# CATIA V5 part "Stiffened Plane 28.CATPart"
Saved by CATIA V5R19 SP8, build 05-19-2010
Part number: Stiffened Plane 28
Bounding box of the stored display mesh (mm): x -20 to 20, y 795 to 1210.536, z 380 to 458.19
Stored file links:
  G:\EU_thinkMotion\CFAO_2010\MMS_groupe3\MMS_groupe3\A reprendre\fovide\fovide\Stiffened Plane 28.CATPart
  G:\EU_thinkMotion\CFAO_2010\MMS_groupe3\MMS_groupe3\A reprendre\fovide\fovide\fovide.CATProduct
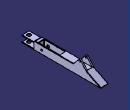
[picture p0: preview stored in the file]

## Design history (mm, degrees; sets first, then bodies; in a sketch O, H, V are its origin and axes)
Set1
  Plane1: linked copy from another document
  Line1 to Line3: linked copy from another document
  Point1 "Point.E": linked copy from another document
  Line4: linked copy from another document
Body1 (main body)
  Sketch1 on Plane1, origin (0, 0, 0), H (0, 1, 0), V (0, 0, 1)
    line L1 (865, 422) -> (1132.4619, 422)
    line L2 (1132.4619, 422) -> (1217.1203, 380)
    line L3 (1217.1203, 380) -> (865, 380)
    reference projected line E1 (1100, 400) -> (815, 400) from Line1
    line L4 (865, 422) -> (857, 416)
    line L5 (857, 416) -> (795, 416)
    line L6 (795, 416) -> (795, 411)
    line L7 (795, 411) -> (857.1371, 411)
    line L8 (857.1371, 411) -> (857.1371, 385)
    line L9 (857.1371, 385) -> (795, 385)
    point P10 (795, 385)
    line L10 (795, 385) -> (795, 380)
    point P11 (795, 380)
    line L11 (795, 380) -> (865, 380)
    reference projected line E2 (815, 250) -> (815, 550) from Line2
    distance L1 E1 = 22
    length L5 = 62
    distance L6 E2 = 20
    length L8 = 26
    length L6 = 5
    length L10 = 5
    distance L1 L3 = 42
    horizontal: L1 H, L3 H, L5 H, L7 H, L9 H, L11 H
    vertical: L6 V, L8 V, L10 V
    coincidence: P10 L6, P11 L3
  Pad1: profile Sketch1, direction (1, 0, 0), length 20, mirrored extent
  Sketch2 on face of Pad1 from Sketch1.L1, origin (0, 0, 422), H (1, 0, 0), V (0, 1, 0)
    line L1 (-14, 990) -> (14, 990)
    line L2 (14, 990) -> (14, 880)
    line L3 (14, 880) -> (-14, 880)
    line L4 (-14, 880) -> (-14, 990)
    reference projected line E1 (0, 1100) -> (0, 815) from Line1
    reference projected line E2 (-150, 900) -> (150, 900) from Line3
    distance L2 E1 = 14
    distance L2 L4 = 28
    length L2 = 110
    distance L3 E2 = 20
    horizontal: L1 H, L3 H
    vertical: L2 V, L4 V
  Pocket1: profile Sketch2, direction (0, 0, -1), length 35
  Sketch3 on end face of Pad1, origin (20, 900, 400), H (0, 1, 0), V (0, 0, 1)
    point P1 (0, 0)
    intersected point E1 (0, 0) from Line3
    coincidence: E1 P1
  Hole1: placed by Sketch3, at (20, 900, 400) direction (-1, 0, 0), diameter 10, through (limit type 3)
  Sketch4 on end face of Pad1, origin (20, 0, 0), H (0, 1, 0), V (0, 0, 1)
    line L1 (1132.4619, 422) -> (1099.9278, 460.9998)
    point P1 (1132.4619, 422)
    point P2 (1099.9278, 460.9998)
    line L2 (1099.9278, 460.9998) -> (1067.4619, 422)
    point P3 (1067.4619, 422)
    line L3 (1067.4619, 422) -> (1132.4619, 422)
    point P4 (1067.4619, 422)
    point P5 (1132.4619, 422)
    reference projected point E1 (1100, 450) from Point1
    reference projected point E2 (1132.4619, 422) from vertex [face of Pad1 from Sketch1.L1 | end face of Pad1 | face of Pad1 from Sketch1.L2]
    length L3 = 65
    distance P2 E1 = 11
    horizontal: L3 H
    coincidence: P3 P4, P1 P5, P1 E2
  Pad2: profile Sketch4, direction (-1, 0, 0), length 7
  Sketch5 on face of Pad2, origin (20, 1100, 450), H (0, 1, 0), V (0, 0, 1)
    point P1 (0, 0)
    intersected point E1 (0, 0) from Line4
    coincidence: E1 P1
  Hole2: placed by Sketch5, at (20, 1100, 450) direction (-1, 0, 0), diameter 10, through (limit type 3)
  Fillet1: radius 5, on edge [face of Pad2 from Sketch4.L1 | face of Pad2 from Sketch4.L2]
  Sketch6 on start face of Pad1, origin (-20, 0, 0), H (0, -1, 0), V (0, 0, 1)
    line L1 (-1132.4619, 422) -> (-1067.4619, 422)
    point P1 (-1132.4619, 422)
    line L2 (-1067.4619, 422) -> (-1100.0106, 461)
    point P3 (-1100.0106, 461)
    line L3 (-1100.0106, 461) -> (-1132.4619, 422)
    reference projected point E1 (-1132.4619, 422) from vertex [face of Pad1 from Sketch1.L1 | start face of Pad1 | face of Pad1 from Sketch1.L2]
    reference projected point E2 (-1100, 450) from Point1
    length L1 = 65
    distance P3 E2 = 11
    horizontal: L1 H
    coincidence: P1 E1
  Pad3: profile Sketch6, direction (1, 0, 0), length 7
  Sketch7 on face of Pad3, origin (-20, 1100, 450), H (0, 1, 0), V (0, 0, -1)
    point P1 (0, 0)
    intersected point E1 (0, 0) from Line4
    coincidence: E1 P1
  Hole3: placed by Sketch7, at (-20, 1100, 450) direction (1, 0, 0), diameter 10, through (limit type 3)
  Fillet2: radius 5, on edge [face of Pad3 from Sketch6.L2 | face of Pad3 from Sketch6.L3]
  Sketch8 on face of Pad1 from Sketch1.L5, origin (0, 815, 416), H (1, 0, 0), V (0, 1, 0)
    point P1 (0, 0)
    intersected point E1 (0, 0) from Line2
    coincidence: E1 P1
  Hole4: placed by Sketch8, at (0, 815, 416) direction (0, 0, -1), diameter 20, through (limit type 3)
  Fillet3: radius 2, on face of Pad1 from Sketch1.L3; face of Pad1 from Sketch1.L2; face of Pocket1 from Sketch2.L4; face of Pocket1 from Sketch2.L1; face of Pocket1 from Sketch2.L3; face of Pocket1 from Sketch2.L2; edge [face of Pad1 from Sketch1.L5 | face of Pad1 from Sketch1.L4]; edge [face of Pad3 | face of Pad1 from Sketch1.L5]; edge [face of Pad1 from Sketch1.L6 | face of Pad1 from Sketch1.L5]; edge [face of Pad1 from Sketch1.L5 | face of Pad2]; edge [face of Pad1 from Sketch1.L7 | face of Pad2]; edge [face of Pad1 from Sketch1.L8 | face of Pad1 from Sketch1.L7]; edge [face of Pad3 | face of Pad1 from Sketch1.L7]; edge [face of Pad1 from Sketch1.L7 | face of Pad1 from Sketch1.L6]; edge [face of Pad3 | face of Pad1 from Sketch1.L9]; edge [face of Pad1 from Sketch1.L9 | face of Pad1 from Sketch1.L8]; edge [face of Pad1 from Sketch1.L9 | face of Pad2]; edge [face of Pad1 from Sketch1.L10 | face of Pad1 from Sketch1.L9]
  Fillet4: radius 2, on edge [face of Pad1 from Sketch1.L1 | face of Pad2]; edge [face of Pad1 from Sketch1.L4 | face of Pad1 from Sketch1.L1]; edge [face of Pad3 | face of Pad1 from Sketch1.L1]; edge [face of Pad2 | face of Pad1 from Sketch1.L4]; edge [face of Pad3 | face of Pad1 from Sketch1.L4]; edge [face of Pad2 | face of Pad1 from Sketch1.L8]; edge [face of Pad3 | face of Pad1 from Sketch1.L8]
